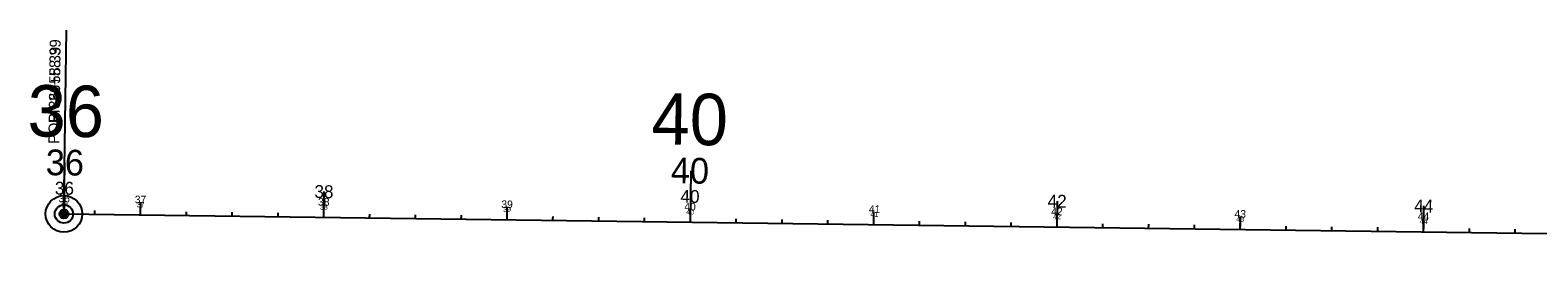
# Model space of a CAD drawing. Extents: x 564646 to 607088, y 225853 to 261760.
# Drawn here: x 597450 to 598272, y 249655 to 249789 of the extents above; entities that cross this region are included whole.
import ezdxf

# ---------------------------------------------------------------- set-up
doc = ezdxf.new("R2010")
doc.units = 0
for name, color, linetype in [('B_CONC_HIDDEN_LT', 7, 'Continuous'), ('B_CONST', 7, 'Continuous'), ('B_EXIST', 7, 'Continuous'), ('B_TEXT', 7, 'Continuous'), ('E-Easements', 7, 'Continuous'), ('E-Property Lines', 7, 'Continuous'), ('E_ALI_100', 7, 'Continuous'), ('E_RW_CorporateLimits', 7, 'Continuous'), ('E_WTR_FlowLine', 7, 'Continuous'), ('EMCS_SURVEY_PT CODES', 7, 'Continuous'), ('EMCS_SURVEY_PT ELEV', 7, 'Continuous'), ('EMCS_SURVEY_PT NOTES', 7, 'Continuous'), ('P-Easements Floodplain', 7, 'Continuous'), ('P-Easements Temporary', 7, 'Continuous'), ('P_ALI_100_Tic', 7, 'Continuous'), ('P_ALI_20', 7, 'Continuous'), ('P_ALI_50', 7, 'Continuous'), ('P_RW_AccessPreviousProject Txt', 7, 'Continuous'), ('P_RW_EasementPerm', 7, 'Continuous'), ('P_RW_EasementTemp', 7, 'Continuous'), ('P_RW_PropertyConnector', 7, 'Continuous'), ('P_RW_Proposed', 7, 'Continuous'), ('P_WAL', 7, 'Continuous')]:
    doc.layers.add(name, color=color, linetype=linetype)

msp = doc.modelspace()

# ---------------------------------------------------------------- linework, layer by layer
at = {"layer": 'B_CONC_HIDDEN_LT'}
msp.add_line((597468.21, 249689.24), (600131.55, 249654.51), dxfattribs=at)
msp.add_line((597468.21, 249689.24), (600131.55, 249654.51), dxfattribs=at)
at = {"layer": 'B_CONST'}
msp.add_circle((597468.21, 249689.24), 1.5, dxfattribs=at)
at = {"layer": 'B_EXIST'}
msp.add_circle((597468.21, 249689.24), 5, dxfattribs=at)
at = {"layer": 'B_TEXT'}
msp.add_lwpolyline([(597468.21, 249689.24), (597469.52, 249789.23)], dxfattribs=at)
at = {"layer": 'E-Easements'}
msp.add_circle((597468.21, 249689.24), 2.5, dxfattribs=at)
at = {"layer": 'E_ALI_100'}
for points in [[(597468.25, 249692.04), (597468.21, 249689.24)], [(597509.86, 249691.5), (597509.82, 249688.7)], [(597468.23, 249690.64), (597468.21, 249689.24)], [(597484.84, 249690.42), (597484.82, 249689.02)], [(597534.84, 249689.77), (597534.82, 249688.37)], [(597559.83, 249689.45), (597559.82, 249688.05)], [(597584.83, 249689.12), (597584.81, 249687.72)], [(597609.85, 249690.19), (597609.81, 249687.39)], [(597634.83, 249688.47), (597634.81, 249687.07)], [(597659.83, 249688.14), (597659.81, 249686.74)], [(597684.82, 249687.82), (597684.81, 249686.42)], [(597709.84, 249688.89), (597709.8, 249686.09)], [(597734.82, 249687.16), (597734.8, 249685.76)], [(597759.82, 249686.84), (597759.8, 249685.44)], [(597784.82, 249686.51), (597784.8, 249685.11)], [(597809.83, 249687.59), (597809.79, 249684.79)], [(597834.81, 249685.86), (597834.79, 249684.46)], [(597859.81, 249685.53), (597859.79, 249684.13)], [(597884.81, 249685.21), (597884.79, 249683.81)], [(597909.82, 249686.28), (597909.79, 249683.48)], [(597934.8, 249684.56), (597934.78, 249683.16)], [(597959.8, 249684.23), (597959.78, 249682.83)], [(597984.8, 249683.9), (597984.78, 249682.5)], [(598009.81, 249684.98), (598009.78, 249682.18)], [(598034.79, 249683.25), (598034.78, 249681.85)], [(598109.81, 249683.67), (598109.77, 249680.87)], [(598059.79, 249682.93), (598059.77, 249681.53)], [(598084.79, 249682.6), (598084.77, 249681.2)], [(598134.79, 249681.95), (598134.77, 249680.55)], [(598159.78, 249681.62), (598159.77, 249680.22)], [(598184.78, 249681.3), (598184.76, 249679.9)], [(598209.8, 249682.37), (598209.76, 249679.57)], [(598234.78, 249680.64), (598234.76, 249679.24)], [(598259.77, 249680.32), (598259.76, 249678.92)]]:
    msp.add_lwpolyline(points, dxfattribs=at)
at = {"layer": 'E_WTR_FlowLine'}
msp.add_circle((597468.21, 249689.24), 0.5, dxfattribs=at)
at = {"layer": 'EMCS_SURVEY_PT CODES'}
msp.add_line((597468.21, 249689.24), (600131.55, 249654.51), dxfattribs=at)
at = {"layer": 'EMCS_SURVEY_PT ELEV'}
msp.add_line((597468.21, 249689.24), (600131.55, 249654.51), dxfattribs=at)
at = {"layer": 'P-Easements Floodplain'}
msp.add_line((597468.21, 249689.24), (600131.55, 249654.51), dxfattribs=at)
at = {"layer": 'P-Easements Temporary'}
msp.add_circle((597468.21, 249689.24), 10, dxfattribs=at)
at = {"layer": 'P_ALI_100_Tic'}
for points in [[(597468.58, 249717.24), (597468.21, 249689.24)], [(597810.16, 249712.78), (597809.79, 249684.79)], [(597468.4, 249703.24), (597468.21, 249689.24)], [(597609.99, 249701.39), (597609.81, 249687.39)], [(598009.96, 249696.18), (598009.78, 249682.18)], [(598209.94, 249693.57), (598209.76, 249679.57)]]:
    msp.add_lwpolyline(points, dxfattribs=at)
at = {"layer": 'P_ALI_20'}
for points in [[(597468.4, 249703.24), (597468.21, 249689.24)], [(597468.31, 249696.24), (597468.21, 249689.24)], [(597509.91, 249695.7), (597509.82, 249688.7)], [(597609.9, 249694.39), (597609.81, 249687.39)], [(597709.89, 249693.09), (597709.8, 249686.09)], [(597809.98, 249698.79), (597809.79, 249684.79)], [(597909.88, 249690.48), (597909.79, 249683.48)], [(598009.87, 249689.18), (598009.78, 249682.18)], [(598109.86, 249687.87), (598109.77, 249680.87)], [(598209.85, 249686.57), (598209.76, 249679.57)]]:
    msp.add_lwpolyline(points, dxfattribs=at)
at = {"layer": 'P_ALI_50'}
msp.add_lwpolyline([(597468.21, 249689.24), (597469.52, 249789.23)], dxfattribs=at)
at = {"layer": 'P_RW_AccessPreviousProject Txt'}
for points in [[(597468.27, 249693.44), (597468.21, 249689.24)], [(597468.24, 249691.34), (597468.21, 249689.24)], [(597509.88, 249692.9), (597509.82, 249688.7)], [(597609.87, 249691.59), (597609.81, 249687.39)], [(597484.85, 249691.12), (597484.82, 249689.02)], [(597534.85, 249690.47), (597534.82, 249688.37)], [(597559.84, 249690.15), (597559.82, 249688.05)], [(597584.84, 249689.82), (597584.81, 249687.72)], [(597634.84, 249689.17), (597634.81, 249687.07)], [(597659.84, 249688.84), (597659.81, 249686.74)], [(597684.83, 249688.52), (597684.81, 249686.42)], [(597709.86, 249690.29), (597709.8, 249686.09)], [(597734.83, 249687.86), (597734.8, 249685.76)], [(597759.83, 249687.54), (597759.8, 249685.44)], [(597784.82, 249687.21), (597784.8, 249685.11)], [(597809.85, 249688.99), (597809.79, 249684.79)], [(597834.82, 249686.56), (597834.79, 249684.46)], [(597859.82, 249686.23), (597859.79, 249684.13)], [(597884.82, 249685.91), (597884.79, 249683.81)], [(597909.84, 249687.68), (597909.79, 249683.48)], [(597934.81, 249685.26), (597934.78, 249683.16)], [(597959.81, 249684.93), (597959.78, 249682.83)], [(597984.81, 249684.6), (597984.78, 249682.5)], [(598009.83, 249686.38), (598009.78, 249682.18)], [(598034.8, 249683.95), (598034.78, 249681.85)], [(598059.8, 249683.63), (598059.77, 249681.53)], [(598084.8, 249683.3), (598084.77, 249681.2)], [(598109.82, 249685.07), (598109.77, 249680.87)], [(598209.82, 249683.77), (598209.76, 249679.57)], [(598134.79, 249682.65), (598134.77, 249680.55)], [(598159.79, 249682.32), (598159.77, 249680.22)], [(598184.79, 249682), (598184.76, 249679.9)], [(598234.79, 249681.34), (598234.76, 249679.24)], [(598259.78, 249681.02), (598259.76, 249678.92)]]:
    msp.add_lwpolyline(points, dxfattribs=at)
at = {"layer": 'P_RW_EasementPerm'}
for points in [[(597468.31, 249696.24), (597468.21, 249689.24)], [(597468.26, 249692.74), (597468.21, 249689.24)], [(597509.87, 249692.2), (597509.82, 249688.7)], [(597609.9, 249694.39), (597609.81, 249687.39)], [(597809.89, 249691.79), (597809.79, 249684.79)], [(597709.85, 249689.59), (597709.8, 249686.09)], [(597909.83, 249686.98), (597909.79, 249683.48)], [(598009.87, 249689.18), (598009.78, 249682.18)], [(598109.82, 249684.37), (598109.77, 249680.87)], [(598209.85, 249686.57), (598209.76, 249679.57)]]:
    msp.add_lwpolyline(points, dxfattribs=at)
at = {"layer": 'P_RW_EasementTemp'}
msp.add_line((597468.21, 249689.24), (600131.55, 249654.51), dxfattribs=at)
at = {"layer": 'P_RW_PropertyConnector'}
msp.add_line((597468.21, 249689.24), (600131.55, 249654.51), dxfattribs=at)
at = {"layer": 'P_WAL'}
msp.add_circle((597468.21, 249689.24), 1, dxfattribs=at)
msp.add_circle((597468.21, 249689.24), 1, dxfattribs=at)

# ---------------------------------------------------------------- texts
for s, p in [('36', (597466.22, 249693.47)), ('37', (597507.83, 249692.92)), ('38', (597607.82, 249691.62)), ('39', (597707.81, 249690.32)), ('40', (597807.68, 249689.01)), ('41', (597908.14, 249687.7)), ('42', (598007.78, 249686.4)), ('43', (598107.77, 249685.1)), ('44', (598207.77, 249683.8))]:
    msp.add_text(s, height=2.8, rotation=359.25282).set_placement(p)
at = {"layer": 'B_TEXT'}
msp.add_text('POB 36+58.39', height=6, rotation=89.25282, dxfattribs=at).set_placement((597465.71, 249727.3))
at = {"layer": 'E-Property Lines'}
for s, p in [('36', (597448.26, 249731.5)), ('40', (597788.63, 249727.07))]:
    msp.add_text(s, height=28, rotation=359.25282, dxfattribs=at).set_placement(p)
at = {"layer": 'E_RW_CorporateLimits'}
for s, p in [('36', (597458.24, 249710.37)), ('40', (597799.21, 249705.93))]:
    msp.add_text(s, height=14, rotation=359.25282, dxfattribs=at).set_placement(p)
at = {"layer": 'EMCS_SURVEY_PT NOTES'}
for s, p in [('36', (597465.22, 249695.58)), ('37', (597506.83, 249695.04)), ('38', (597606.82, 249693.73)), ('39', (597706.81, 249692.43)), ('40', (597806.62, 249691.13)), ('41', (597907.32, 249689.81)), ('42', (598006.78, 249688.52)), ('43', (598106.78, 249687.21)), ('44', (598206.77, 249685.91))]:
    msp.add_text(s, height=4.2, rotation=359.25282, dxfattribs=at).set_placement(p)
at = {"layer": 'P_ALI_50'}
msp.add_text('PI  36+58.39', height=6, rotation=89.25282, dxfattribs=at).set_placement((597465.86, 249738.54))
at = {"layer": 'P_RW_Proposed'}
for s, p in [('36', (597463.23, 249699.81)), ('38', (597604.82, 249697.96)), ('40', (597804.5, 249695.36)), ('42', (598004.79, 249692.74)), ('44', (598204.77, 249690.14))]:
    msp.add_text(s, height=7, rotation=359.25282, dxfattribs=at).set_placement(p)

doc.saveas('drawing.dxf')
